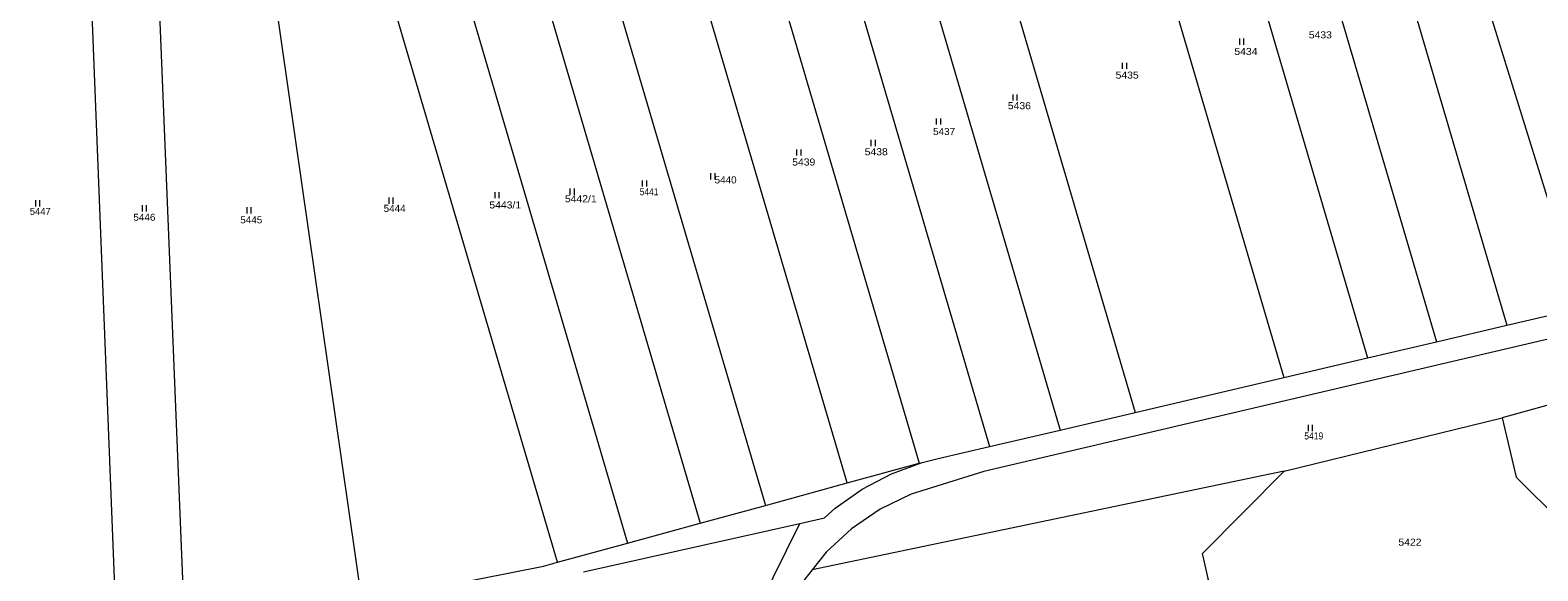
# Model space of a CAD drawing. Extents: x -590528 to -586543, y -1119609 to -1116685.
# Drawn here: x -589033.9 to -588671, y -1118913.5 to -1118783.3 of the extents above; entities that cross this region are included whole.
import ezdxf

# ---------------------------------------------------------------- set-up
doc = ezdxf.new("R2010")
doc.units = 0
doc.header["$LTSCALE"] = 0.68
for name, color, linetype, lineweight in [('1', 7, 'Continuous', 13), ('3', 7, 'Continuous', 13), ('6', 7, 'Continuous', 13)]:
    doc.layers.add(name, color=color, linetype=linetype, lineweight=lineweight)

msp = doc.modelspace()

# ---------------------------------------------------------------- linework, layer by layer
at = {"layer": '1'}
for p, q in [((-588726.22, -1118691.75), (-588678.42, -1118854.34)), ((-588742.7, -1118697.42), (-588695.39, -1118858.32)), ((-588758.81, -1118702.96), (-588711.98, -1118862.22)), ((-588813.05, -1118721.57), (-588767.86, -1118875.33)), ((-588847.23, -1118732.97), (-588802.97, -1118883.56)), ((-589020.72, -1118737.84), (-589013.02, -1118932.18)), ((-588863.75, -1118738.48), (-588819.92, -1118887.57)), ((-588996.6, -1118928.49), (-589004.21, -1118742.32)), ((-588837.23, -1118892.31), (-588880.78, -1118744.18)), ((-588978.98, -1118747.58), (-588954.04, -1118920.98)), ((-588900.13, -1118750.77), (-588856.91, -1118897.71)), ((-588906.98, -1118911.42), (-588953.68, -1118752.65)), ((-588934.65, -1118755.2), (-588890.07, -1118906.79)), ((-588916.26, -1118753.66), (-588872.63, -1118902.01)), ((-588629, -1118848.43), (-588804.33, -1118889.55)), ((-588695.39, -1118858.32), (-588678.42, -1118854.34)), ((-588711.98, -1118862.22), (-588695.39, -1118858.32)), ((-588622.36, -1118860.76), (-588679.52, -1118876.66)), ((-588767.86, -1118875.33), (-588732.07, -1118866.93)), ((-588732.01, -1118889.5), (-588679.52, -1118876.66)), ((-588802.97, -1118883.56), (-588785.91, -1118879.56)), ((-588837.23, -1118892.31), (-588819.92, -1118887.57)), ((-588856.91, -1118897.71), (-588837.23, -1118892.31)), ((-588872.63, -1118902.01), (-588856.91, -1118897.71)), ((-588900.71, -1118913.73), (-588848.6, -1118902.04)), ((-588890.07, -1118906.79), (-588872.63, -1118902.01)), ((-588886.51, -1118978.66), (-588848.6, -1118902.04)), ((-588906.98, -1118911.42), (-588890.07, -1118906.79))]:
    msp.add_line(p, q, dxfattribs=at)
for points in [[(-588778.33, -1118709.68), (-588732.07, -1118866.93), (-588711.98, -1118862.22)], [(-588830.64, -1118727.44), (-588785.91, -1118879.56), (-588767.86, -1118875.33)], [(-588683.78, -1118774.9), (-588660.47, -1118850.13), (-588636.3, -1118844.46)], [(-588678.42, -1118854.34), (-588661.5, -1118850.37), (-588660.47, -1118850.13)], [(-588679.52, -1118876.66), (-588676.15, -1118890.88), (-588665.31, -1118901.67), (-588661.1, -1118906.24), (-588658.66, -1118911.67), (-588658.58, -1118917.9), (-588660.73, -1118923.42), (-588665.2, -1118927.97), (-588671.06, -1118930.31), (-588675.75, -1118934.26), (-588677.28, -1118937.29), (-588677.15, -1118943.53), (-588675.61, -1118949.4), (-588674.47, -1118954.31), (-588671.41, -1118967.19)], [(-588819.92, -1118887.57), (-588819.15, -1118887.36), (-588815.29, -1118886.45), (-588802.97, -1118883.56)], [(-588732.01, -1118889.5), (-588845.61, -1118913.23), (-588847.43, -1118915.5), (-588851.63, -1118922.72), (-588856.18, -1118931.3), (-588882.51, -1118984.91)], [(-588848.6, -1118902.04), (-588842.67, -1118900.71), (-588840.11, -1118898.38), (-588833.61, -1118893.83), (-588826.58, -1118890.14), (-588819.15, -1118887.36)], [(-588804.33, -1118889.55), (-588821.79, -1118895.01), (-588829.27, -1118898.65), (-588836.14, -1118903.35), (-588842.24, -1118909.01), (-588845.61, -1118913.23)], [(-588741.34, -1118975.98), (-588745.99, -1118957.05), (-588754.51, -1118916.52), (-588750.23, -1118915.66), (-588751.7, -1118909.26), (-588732.01, -1118889.5)], [(-588954.04, -1118920.98), (-588933.42, -1118916.94), (-588910.34, -1118912.34), (-588906.98, -1118911.42)]]:
    msp.add_lwpolyline(points, dxfattribs=at)
at = {"layer": '6'}
for p, q in [((-588742.72, -1118786.8), (-588742.72, -1118785.3)), ((-588741.72, -1118786.8), (-588741.72, -1118785.3)), ((-588770.93, -1118792.61), (-588770.93, -1118791.11)), ((-588769.93, -1118792.61), (-588769.93, -1118791.11)), ((-588797.29, -1118800.24), (-588797.29, -1118798.74)), ((-588796.29, -1118800.24), (-588796.29, -1118798.74)), ((-588815.69, -1118806.03), (-588815.69, -1118804.53)), ((-588814.69, -1118806.03), (-588814.69, -1118804.53)), ((-588831.43, -1118811.17), (-588831.43, -1118809.67)), ((-588830.43, -1118811.17), (-588830.43, -1118809.67)), ((-588849.33, -1118813.49), (-588849.33, -1118811.99)), ((-588848.33, -1118813.49), (-588848.33, -1118811.99)), ((-588886.47, -1118820.95), (-588886.47, -1118819.45)), ((-588885.47, -1118820.95), (-588885.47, -1118819.45)), ((-588870.03, -1118819.23), (-588870.03, -1118817.73)), ((-588869.03, -1118819.23), (-588869.03, -1118817.73)), ((-589032.55, -1118825.75), (-589032.55, -1118824.25)), ((-589031.55, -1118825.75), (-589031.55, -1118824.25)), ((-588947.5, -1118825.09), (-588947.5, -1118823.59)), ((-588946.5, -1118825.09), (-588946.5, -1118823.59)), ((-588921.96, -1118823.76), (-588921.96, -1118822.26)), ((-588920.96, -1118823.76), (-588920.96, -1118822.26)), ((-588903.89, -1118822.94), (-588903.89, -1118821.44)), ((-588902.89, -1118822.94), (-588902.89, -1118821.44)), ((-589006.85, -1118826.91), (-589006.85, -1118825.41)), ((-589005.85, -1118826.91), (-589005.85, -1118825.41)), ((-588981.66, -1118827.41), (-588981.66, -1118825.91)), ((-588980.66, -1118827.41), (-588980.66, -1118825.91)), ((-588726.17, -1118879.85), (-588726.17, -1118878.35)), ((-588725.17, -1118879.85), (-588725.17, -1118878.35))]:
    msp.add_line(p, q, dxfattribs=at)

# ---------------------------------------------------------------- texts
at = {"layer": '3'}
for s, width, p in [('5433', 1.1, (-588726.093, -1118785.25)), ('5434', 1.1, (-588744.013, -1118789.25)), ('5435', 1.1, (-588772.603, -1118794.94)), ('5436', 1.1, (-588798.543, -1118802.31)), ('5437', 1.05, (-588816.553, -1118808.53)), ('5438', 1.1, (-588833.003, -1118813.4)), ('5439', 1.1, (-588850.453, -1118815.87)), ('5440', 1.05, (-588869.143, -1118820.18)), ('5443/1', 1.1, (-588923.353, -1118826.21)), ('5442/1', 1.1, (-588905.163, -1118824.72)), ('5441', 0.9, (-588887.173, -1118823.03)), ('5446', 1.05, (-589009.043, -1118829.18)), ('5445', 1.05, (-588983.323, -1118829.8)), ('5444', 1.05, (-588948.803, -1118827.03)), ('5419', 0.9, (-588727.183, -1118881.84)), ('5422', 1.1, (-588704.523, -1118907.43))]:
    msp.add_text(s, height=1.7, dxfattribs=dict(at, width=width)).set_placement(p)
msp.add_text('5447', height=1.7, dxfattribs=at).set_placement((-589033.983, -1118827.76))

doc.saveas('drawing.dxf')
